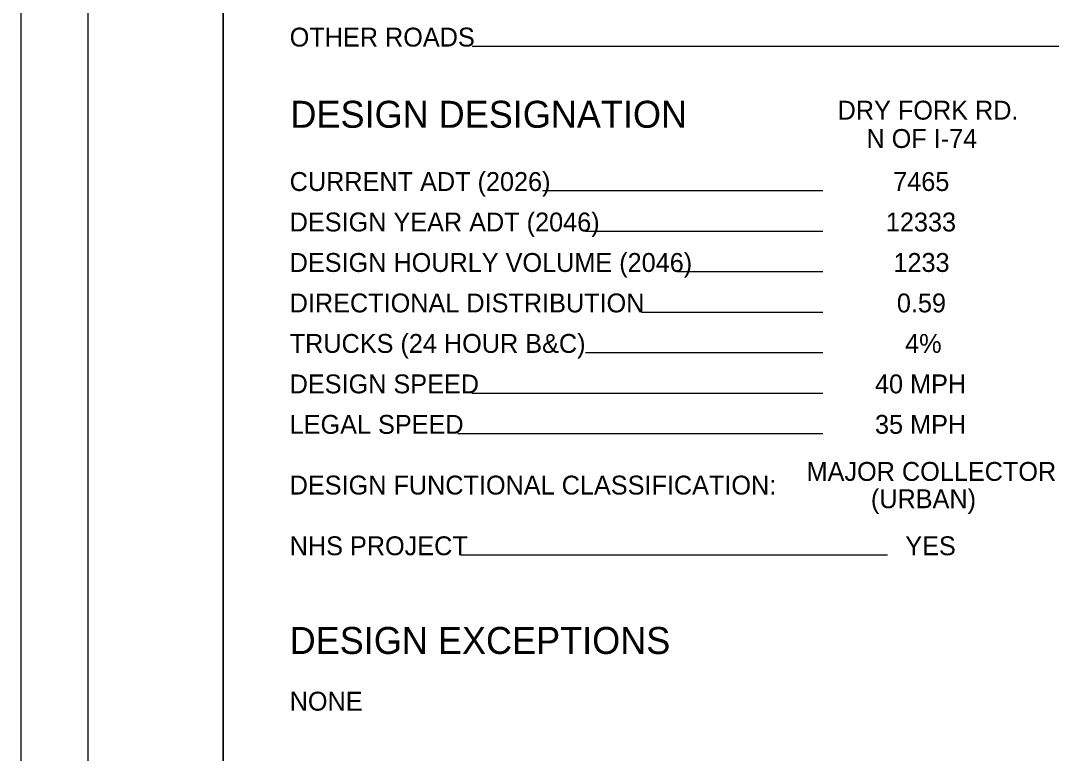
# Model space of a CAD drawing. Extents: x -7.5 to 26.5, y 3.5 to 25.5.
# Drawn here: x -7.46 to 0.27, y 9.14 to 14.57 of the extents above; entities that cross this region are included whole.
import ezdxf

# ---------------------------------------------------------------- set-up
doc = ezdxf.new("R2010")
doc.units = 0
for name, color, linetype in [('SH_Border', 7, 'Continuous'), ('SH_Cut_Line', 7, 'Continuous'), ('SH_Data', 7, 'Continuous'), ('SH_Text', 7, 'Continuous')]:
    doc.layers.add(name, color=color, linetype=linetype)

msp = doc.modelspace()

# ---------------------------------------------------------------- linework, layer by layer
at = {"layer": 'SH_Border'}
for points in [[(-6.9569, 25), (-5.9569, 25), (-5.9569, 4), (-6.9569, 4)], [(-5.9569, 25), (26.0431, 25), (26.0431, 4), (-5.9569, 4)]]:
    msp.add_lwpolyline(points, close=True, dxfattribs=at)
at = {"layer": 'SH_Cut_Line'}
msp.add_lwpolyline([(-7.4569, 3.5), (26.5431, 3.5), (26.5431, 25.5), (-7.4569, 25.5)], close=True, dxfattribs=at)
at = {"layer": 'SH_Data'}
for p, q in [((0.2431, 14.3767), (-4.1098, 14.3767)), ((-1.5067, 13.3062), (-3.5859, 13.3062)), ((-1.5067, 13.0062), (-3.2684, 13.0062)), ((-1.5067, 12.7062), (-2.5846, 12.7062)), ((-1.5067, 12.4062), (-2.8533, 12.4062)), ((-1.5067, 12.1062), (-3.2684, 12.1062)), ((-1.5067, 11.8062), (-4.111, 11.8062)), ((-1.5067, 11.5062), (-4.2148, 11.5062)), ((-1.0265, 10.6062), (-4.19, 10.6062))]:
    msp.add_line(p, q, dxfattribs=at)

# ---------------------------------------------------------------- texts
msp.add_text('DESIGN DESIGNATION', height=0.2, dxfattribs=at).set_placement((-5.4569, 13.7747))
at = {"layer": 'SH_Text'}
for s, height, p in [('OTHER ROADS', 0.14, (-5.4625, 14.3767)), ('DRY FORK RD.', 0.14, (-1.3979, 13.8351)), ('N OF I-74', 0.14, (-1.184, 13.6251)), ('CURRENT ADT (2026)', 0.14, (-5.4625, 13.3062)), ('7465', 0.14, (-0.9855, 13.3062)), ('DESIGN YEAR ADT (2046)', 0.14, (-5.4625, 13.0062)), ('12333', 0.14, (-1.0397, 13.0062)), ('DESIGN HOURLY VOLUME (2046)', 0.14, (-5.4625, 12.7062)), ('1233', 0.14, (-0.9838, 12.7062)), ('DIRECTIONAL DISTRIBUTION', 0.14, (-5.4625, 12.4062)), ('0.59', 0.14, (-0.9582, 12.4062)), ('TRUCKS (24 HOUR B&C)', 0.14, (-5.4625, 12.1062)), ('4%', 0.14, (-0.8971, 12.1062)), ('DESIGN SPEED', 0.14, (-5.4625, 11.8062)), ('40 MPH', 0.14, (-1.1205, 11.8062)), ('LEGAL SPEED', 0.14, (-5.4625, 11.5062)), ('35 MPH', 0.14, (-1.1205, 11.5062)), ('MAJOR COLLECTOR', 0.14, (-1.6279, 11.1575)), ('DESIGN FUNCTIONAL CLASSIFICATION:', 0.14, (-5.4625, 11.0562)), ('(URBAN)', 0.14, (-1.151, 10.955)), ('NHS PROJECT', 0.14, (-5.4625, 10.6062)), ('YES', 0.14, (-0.8959, 10.6062)), ('DESIGN EXCEPTIONS', 0.2, (-5.4625, 9.8744)), ('NONE', 0.14, (-5.4625, 9.4544))]:
    msp.add_text(s, height=height, dxfattribs=at).set_placement(p)

doc.saveas('drawing.dxf')
